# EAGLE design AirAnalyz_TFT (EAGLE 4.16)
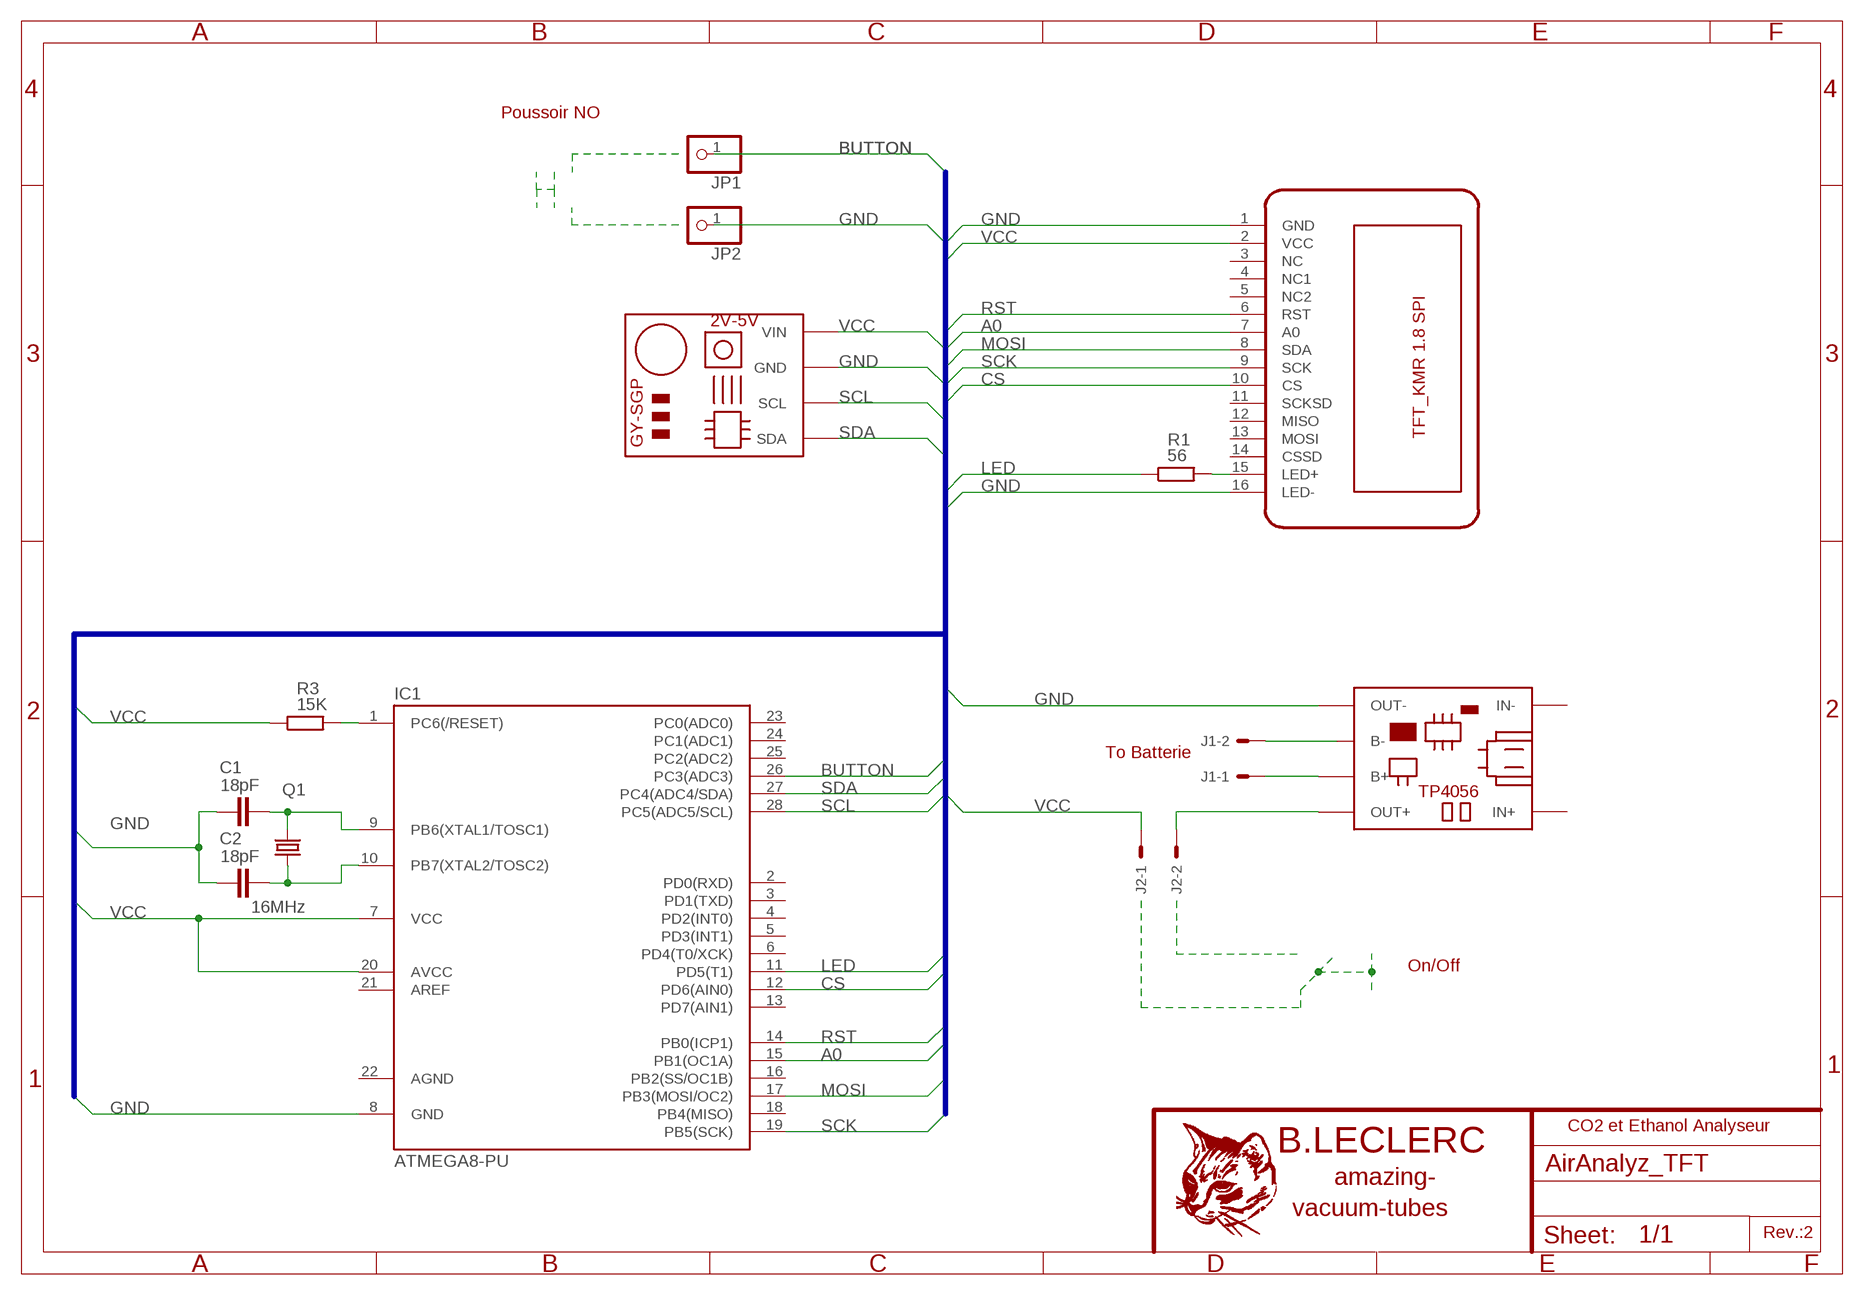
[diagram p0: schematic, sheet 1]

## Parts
C1  18pF  C-EU050-025X075  [C050-025X075]
C2  18pF  C-EU050-025X075  [C050-025X075]
IC1  ATMEGA8-PU  [DIL28-3]
J1  22-27-2021-02  [6410-02]
J2  22-27-2021-02  [6410-02]
JP1  PINHD-1X1  [1X01]
JP2  PINHD-1X1  [1X01]
Q1  16MHz  CRYTALHC49S  [HC49/S]
R1  56  R-EU_0207/12  [0207/12]
R3  15K  R-EU_0207/12  [0207/12]
U$2  TFT_KRM1.8SPI  [TFT_KMR1.8SPI]
U$3  SGP30-AIRANALIZER  [SGP30_AIRANALYZER]
U$4  CHARGEUR_ION-LI  [CHARGEUR_ION-LI]

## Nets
A0: IC1.15(PB1(OC1A)) U$2.7(A0)
BUTTON: IC1.26(PC3(ADC3)) JP1.1
CS: IC1.12(PD6(AIN0)) U$2.10(CS)
GND: C1.1 C2.1 IC1.8(GND) JP2.1 U$2.1(GND) U$2.16(LED-) U$3.GND U$4.OUT-
LED: IC1.11(PD5(T1)) R1.1
LED+: R1.2 U$2.15(LED+)
MOSI: IC1.17(PB3(MOSI/OC2)) U$2.8(SDA)
N$2: J1.2 U$4.B-
N$3: C1.2 IC1.9(PB6(XTAL1/TOSC1)) Q1.2
N$5: IC1.1(PC6(/RESET)) R3.2
N$6: C2.2 IC1.10(PB7(XTAL2/TOSC2)) Q1.1
N$7: J1.1 U$4.B+
N$8: J2.2 U$4.OUT+
RST: IC1.14(PB0(ICP1)) U$2.6(RST)
SCK: IC1.19(PB5(SCK)) U$2.9(SCK)
SCL: IC1.28(PC5(ADC5/SCL)) U$3.SCL
SDA: IC1.27(PC4(ADC4/SDA)) U$3.SDA
VCC: IC1.7(VCC) IC1.20(AVCC) J2.1 R3.1 U$2.2(VCC) U$3.VIN
Unconnected: IC1.2(PD0(RXD)) IC1.3(PD1(TXD)) IC1.4(PD2(INT0)) IC1.5(PD3(INT1)) IC1.6(PD4(T0/XCK)) IC1.13(PD7(AIN1)) IC1.16(PB2(SS/OC1B)) IC1.18(PB4(MISO)) IC1.21(AREF) IC1.23(PC0(ADC0)) IC1.24(PC1(ADC1)) IC1.25(PC2(ADC2)) U$2.3(NC) U$2.4(NC1) U$2.5(NC2) U$2.11(SCKSD) U$2.12(MISO) U$2.13(MOSI) U$2.14(CSSD)

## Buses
B$1

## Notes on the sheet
- Poussoir NO
- To Batterie
- On/Off
- CO2 et Ethanol Analyseur
- Rev.:2

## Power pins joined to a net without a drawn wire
AGND: IC1.22(AGND)
IN+: U$4.IN+
IN-: U$4.IN-

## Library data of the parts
C1 C2 = rcl:C-EU: CAPACITOR, European symbol
IC1 = atmega8:ATMEGA8-PU
J1 J2 = con-molex:22-?-02: CONNECTOR
JP1 JP2 = pinhead:PINHD-1X1: PIN HEADER
Q1 = crystal:CRYTAL: CRYSTAL
R1 R3 = rcl:R-EU_: RESISTOR, European symbol
U$2 = Arduino:TFT_KRM1.8SPI
U$3 = Arduino:SGP30-AIRANALIZER
U$4 = Arduino:CHARGEUR_ION-LI

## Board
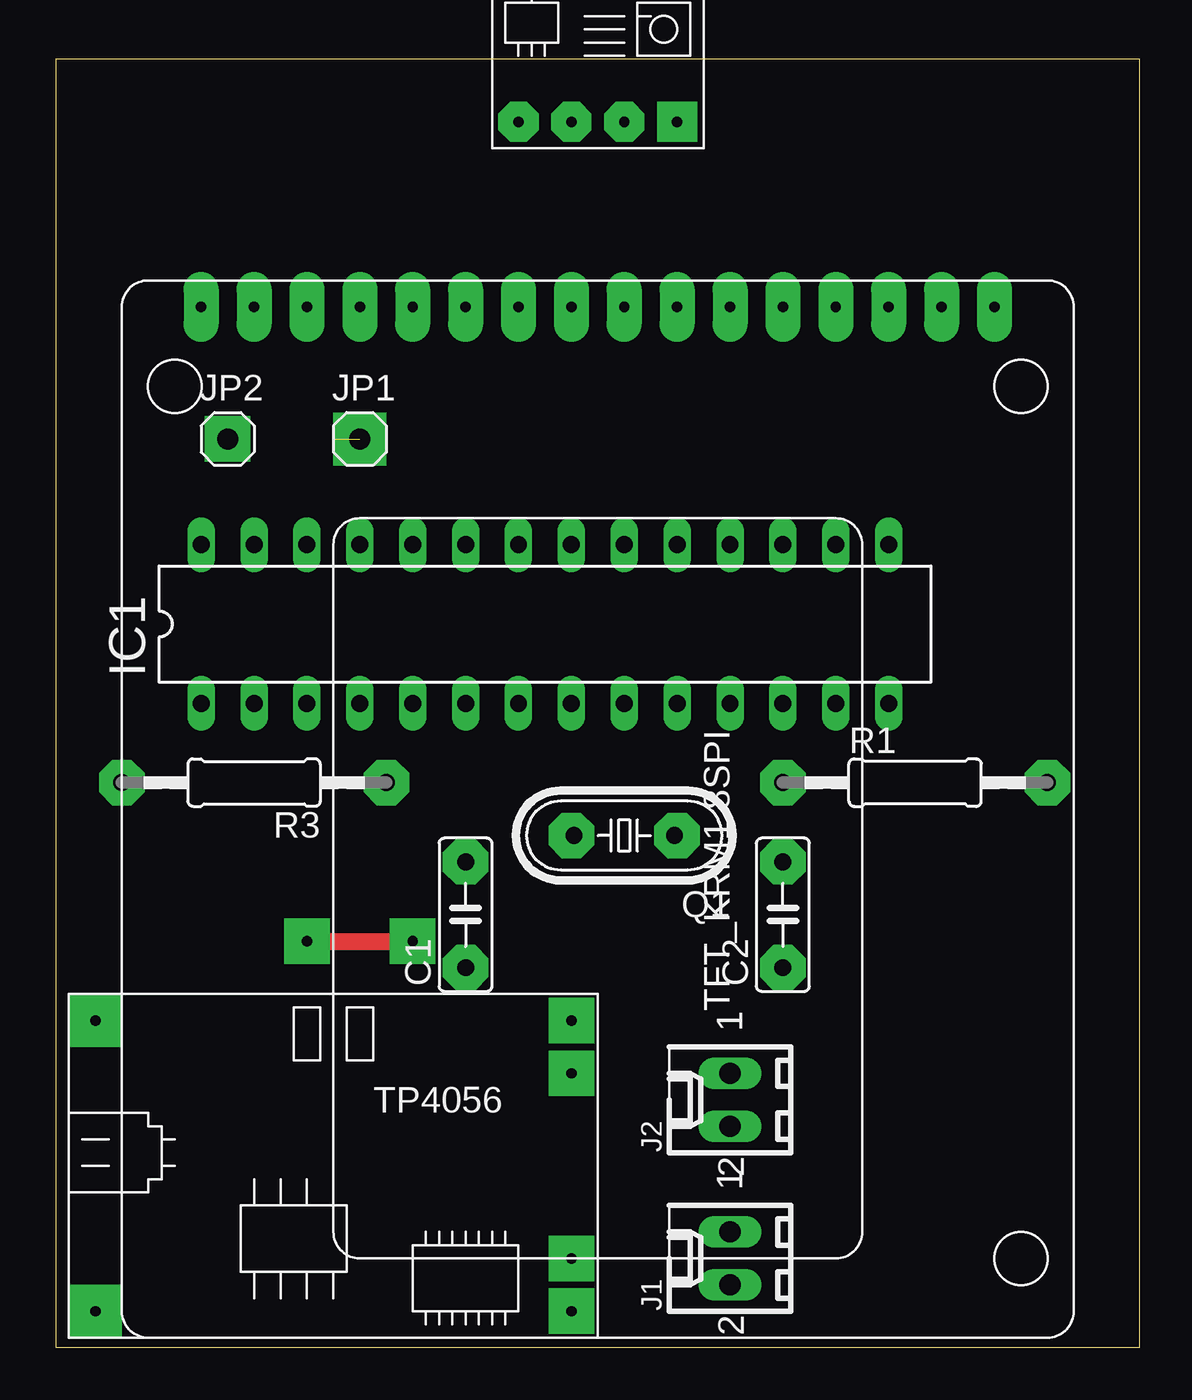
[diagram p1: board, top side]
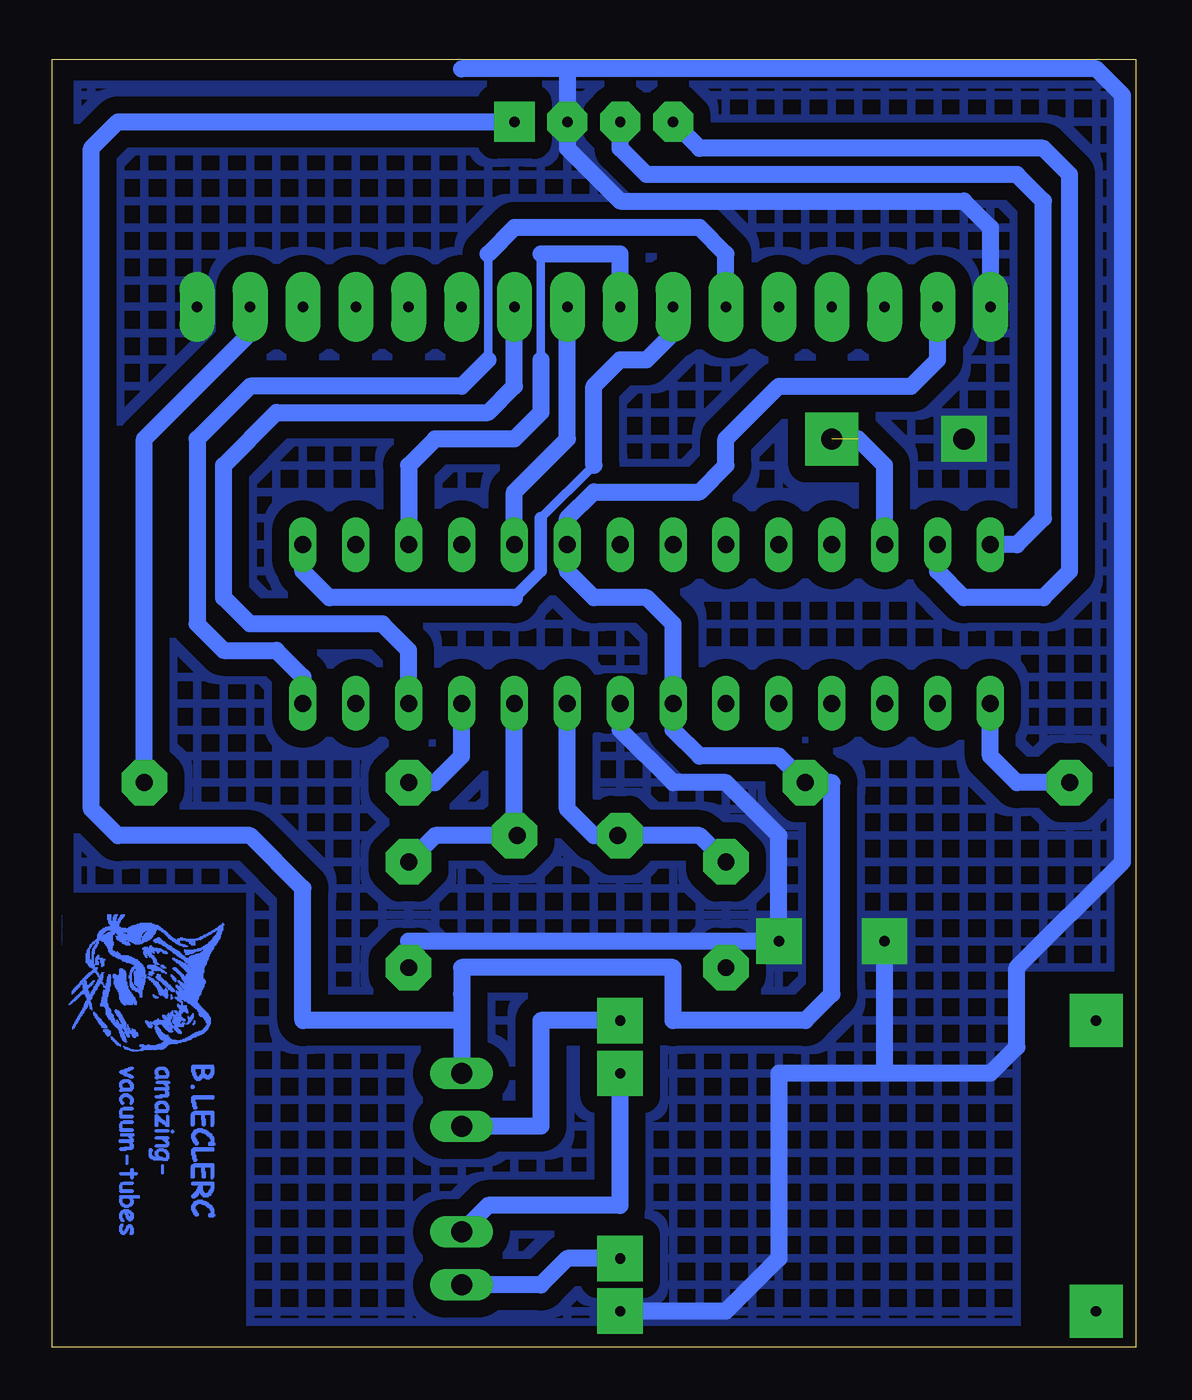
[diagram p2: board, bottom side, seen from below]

Size 52.05 x 61.9 mm. Coordinates in mm from the lower left corner, seen from the top.
Outline: 0,0 52.05,0 52.05,61.9 0,61.9 0,0
Copper layers (1*16): Top 0.035mm / dielectric 1.5mm / Bottom 0.035mm
Design rules "default": minimum track width 10mil, minimum drill 24mil, track to track 8mil, track to pad 8mil, pad to pad 8mil, via to via 8mil, smd to smd 8mil, copper to edge 40mil, drill to drill 8mil, minimum pad ring 10mil, minimum via ring 8mil, stop-mask expansion 4mil, vias tented up to drill 0mil, thermal gap 10mil

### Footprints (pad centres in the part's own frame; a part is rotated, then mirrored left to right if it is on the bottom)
C050-025X075 = drill 0.813 octagon: 1 -2.54,0; 2 2.54,0
DIL28-3 = drill 0.813 long: 1 -16.51,-3.81; 2 -13.97,-3.81; 3 -11.43,-3.81; 4 -8.89,-3.81; 5 -6.35,-3.81; 6 -3.81,-3.81; 7 -1.27,-3.81; 8 1.27,-3.81; 9 3.81,-3.81; 10 6.35,-3.81; 11 8.89,-3.81; 12 11.43,-3.81; 13 13.97,-3.81; 14 16.51,-3.81; 15 16.51,3.81; 16 13.97,3.81; 17 11.43,3.81; 18 8.89,3.81; 19 6.35,3.81; 20 3.81,3.81; 21 1.27,3.81; 22 -1.27,3.81; 23 -3.81,3.81; 24 -6.35,3.81; 25 -8.89,3.81; 26 -11.43,3.81; 27 -13.97,3.81; 28 -16.51,3.81
6410-02 = drill 1.016 long: 1 1.27,0; 2 -1.27,0
1X01 = drill 1.016 octagon: 1 0,0
HC49/S = drill 0.813 round: 1 -2.413,0; 2 2.413,0
0207/12 = drill 0.813 octagon: 1 -6.35,0; 2 6.35,0
TFT_KMR1.8SPI = drill 0.5 pad 1.676 long: 1 -24.13,-19.05; 2 -24.13,-16.51; 3 -24.13,-13.97; 4 -24.13,-11.43; 5 -24.13,-8.89; 6 -24.13,-6.35; 7 -24.13,-3.81; 8 -24.13,-1.27; 9 -24.13,1.27; 10 -24.13,3.81; 11 -24.13,6.35; 12 -24.13,8.89; 13 -24.13,11.43; 14 -24.13,13.97; 15 -24.13,16.51; 16 -24.13,19.05
SGP30_AIRANALYZER = drill 0.5 pad 1.93 octagon: GND 1.27,3.81; SCL 1.27,6.35; SDA 1.27,8.89 | drill 0.5 pad 1.93 square: VIN 1.27,1.27
CHARGEUR_ION-LI = drill 0.5 pad 2.184 square: B+ 24.13,12.7; B- 24.13,3.81; OUT+ 24.13,15.24; OUT- 24.13,1.27 | drill 0.5 pad 2.54 square: IN+ 1.27,15.24; IN- 1.27,1.27

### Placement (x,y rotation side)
C1  19.68,20.79 90 top
C2  34.92,20.79 90 top
IC1  23.49,34.76 0 top
J1  32.38,4.28 90 top
J2  32.38,11.9 90 top
JP1  14.6,43.65 0 top
JP2  8.25,43.65 0 top
Q1  27.3,24.6 180 top
R1  41.27,27.14 0 top
R3  9.52,27.14 180 top
U$2  26.03,25.87 270 top
U$3  31.11,57.62 90 top
U$4  0.63,0.47 0 top
U$5  [CHAT]  51.43,20.79 270 bottom

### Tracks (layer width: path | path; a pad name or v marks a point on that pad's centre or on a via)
A0
  Bottom 0.406: 28.57,39.84 26.03,42.38
  Bottom 0.61: 28.57,39.84 28.57,37.3 29.84,36.03
  Bottom 0.813: U$2.7 22.22,48.73 23.49,47.46 24.76,47.46 26.03,46.19 26.03,42.38 | 29.84,36.03 38.73,36.03 40,37.3 IC1.15
BUTTON  (1 unrouted)
  Bottom 0.813: 13.33,43.65 12.06,42.38 IC1.26
CS
  Bottom 0.813: U$2.10 29.84,46.19 31.11,44.92 41.27,44.92 43.81,42.38 43.81,36.03 42.54,34.76 36.19,34.76 34.92,33.49 IC1.12
GND  (via drill 0.5 pad 2.18)
  Top 0.813: v12.06,19.52 v17.14,19.52
  Bottom 0.813: U$2.1 6.98,53.81 8.25,55.08 24.76,55.08 27.3,57.62 U$3.GND 27.3,61.43 | U$4.OUT- 19.68,1.74 17.14,4.28 17.14,13.17 12.06,13.17 | IC1.8 24.76,29.68 22.22,27.14 19.68,27.14 17.14,24.6 v17.14,19.52 19.68,19.52 | 27.3,61.43 32.38,61.43 | 27.3,61.43 1.9,61.43 0.63,60.16 0.63,23.33 5.71,18.25 5.71,14.44 6.98,13.17 12.06,13.17 | 12.06,13.17 v12.06,19.52 | 19.68,19.52 34.92,19.52 C2.1 | 19.68,19.52 C1.1
  other vias: 8.25,43.65
  pour Bottom (isolate 0.813, no thermals, hatched): 5.71,0.47 5.71,18.25 0.63,18.25 0.63,61.43 51.43,61.43 51.43,22.06 42.54,22.06 42.54,0.47
LED
  Bottom 0.813: IC1.11 32.38,28.41 33.65,27.14 R1.1
LED+
  Bottom 0.813: U$2.15 42.54,48.73 47.62,43.65 R1.2
MOSI
  Bottom 0.406: 28.57,52.54 28.57,47.46
  Bottom 0.813: IC1.17 34.92,42.38 33.65,43.65 29.84,43.65 28.57,44.92 28.57,47.46 | 28.57,52.54 24.76,52.54 U$2.8
N$2
  Bottom 0.813: U$4.B- 27.3,4.28 28.57,3.01 J1.2
N$3
  Bottom 0.813: IC1.9 27.3,25.87 26.03,24.6 Q1.2 20.95,24.6 C1.2
N$5
  Bottom 0.813: IC1.1 6.98,28.41 5.71,27.14 R3.2
N$6
  Bottom 0.813: 29.84,24.6 IC1.10 | Q1.1 29.84,24.6 | 29.84,24.6 33.65,24.6 C2.2
N$7
  Bottom 0.813: U$4.B+ 24.76,6.82 31.11,6.82 J1.1
N$8
  Bottom 0.813: U$4.OUT+ 28.57,15.71 28.57,10.63 J2.2
N$10  (via drill 0.5 pad 1.27)
  other vias: 17.14,38.57
N$11  (via drill 0.5 pad 1.27)
  other vias: 14.6,38.57
N$12  (via drill 0.5 pad 1.27)
  other vias: 19.68,38.57
N$13  (via drill 0.5 pad 1.27)
  other vias: 6.98,30.95
N$14  (via drill 0.5 pad 1.27)
  other vias: 29.84,38.57
N$15  (via drill 0.5 pad 1.27)
  other vias: 12.06,30.95
N$16  (via drill 0.5 pad 1.27)
  other vias: 24.76,38.57
N$17  (via drill 0.5 pad 1.27)
  other vias: 22.22,38.57
N$18  (via drill 0.5 pad 1.27)
  other vias: 27.3,38.57
N$19  (via drill 0.5 pad 1.27)
  other vias: 32.38,38.57
N$20  (via drill 0.5 pad 1.27)
  other vias: 24.76,30.95
N$21  (via drill 0.5 pad 1.27)
  other vias: 19.68,30.95
N$22  (via drill 0.5 pad 1.27)
  other vias: 27.3,30.95
N$23  (via drill 0.5 pad 1.27)
  other vias: 32.38,30.95
N$24  (via drill 0.5 pad 1.27)
  other vias: 34.92,30.95
N$25  (via drill 0.5 pad 1.27)
  other vias: 37.46,38.57
N$26  (via drill 0.5 pad 1.27)
  other vias: 34.92,38.57
N$27  (via drill 0.5 pad 1.27)
  other vias: 40,38.57
N$28  (via drill 0.5 pad 1.27)
  other vias: 40,30.95
N$29  (via drill 0.5 pad 1.27)
  other vias: 37.46,30.95
N$30  (via drill 0.5 pad 1.27)
  other vias: 29.84,30.95
N$31  (via drill 0.5 pad 1.27)
  other vias: 22.22,30.95
N$32  (via drill 0.5 pad 1.27)
  other vias: 17.14,30.95
N$33  (via drill 0.5 pad 1.27)
  other vias: 14.6,30.95
N$34  (via drill 0.5 pad 1.27)
  other vias: 9.52,30.95
N$35  (via drill 0.5 pad 1.27)
  other vias: 12.06,38.57
N$36  (via drill 0.5 pad 1.27)
  other vias: 9.52,38.57
N$37  (via drill 0.5 pad 1.27)
  other vias: 6.98,38.57
N$40  (via drill 0.5 pad 2.18)
  other vias: 15.87,27.14
N$41  (via drill 0.5 pad 2.18)
  other vias: 3.17,27.14
N$42  (via drill 0.5 pad 2.18)
  other vias: 47.62,27.14
N$43  (via drill 0.5 pad 2.18)
  other vias: 34.92,27.14
N$44  (via drill 0.5 pad 2.18)
  other vias: 24.76,24.6
N$45  (via drill 0.5 pad 2.18)
  other vias: 29.84,24.6
N$47  (via drill 0.5 pad 2.18)
  other vias: 19.68,23.33
N$48  (via drill 0.5 pad 2.18)
  other vias: 34.92,23.33
N$50  (via drill 0.5 pad 1.27)
  other vias: 32.38,13.17
N$51  (via drill 0.5 pad 1.27)
  other vias: 32.38,10.63
N$54  (via drill 0.5 pad 1.27)
  other vias: 32.38,5.55
N$55  (via drill 0.5 pad 1.27)
  other vias: 32.38,3.01
N$56  (via drill 0.5 pad 2.54)
  other vias: 14.6,43.65
RST
  Bottom 0.406: 40,32.22 IC1.14 | 31.11,52.54 31.11,47.46
  Bottom 0.813: U$2.6 19.68,52.54 20.95,53.81 29.84,53.81 31.11,52.54 | 31.11,47.46 32.38,46.19 42.54,46.19 45.08,43.65 45.08,34.76 43.81,33.49 41.27,33.49 40,32.22
S$1  (via drill 0.5 pad 2.18)
  other vias: 19.68,18.25
S$2  (via drill 0.5 pad 2.18)
  other vias: 34.92,18.25
SCK
  Bottom 0.813: U$2.9 27.3,43.65 29.84,41.11 IC1.19
SCL
  Bottom 0.813: U$3.SCL 24.76,57.62 23.49,56.35 5.71,56.35 4.44,55.08 4.44,39.84 5.71,38.57 IC1.28
SDA
  Bottom 0.813: IC1.27 9.52,37.3 8.25,36.03 4.44,36.03 3.17,37.3 3.17,56.35 4.44,57.62 20.95,57.62 U$3.SDA
VCC
  Bottom 0.813: U$2.2 9.52,47.46 10.79,46.19 17.14,46.19 19.68,43.65 19.68,42.38 20.95,41.11 26.03,41.11 27.3,39.84 IC1.20 27.3,37.3 26.03,36.03 23.49,36.03 22.22,34.76 IC1.7 22.22,29.68 20.95,28.41 17.14,28.41 R3.1 14.6,27.14 14.6,16.98 15.87,15.71 22.22,15.71 22.22,18.25 32.38,18.25 32.38,16.98 | 32.38,16.98 32.38,15.71 40,15.71 40,22.06 42.54,24.6 48.89,24.6 50.16,25.87 50.16,57.62 48.89,58.89 U$3.VIN | 32.38,16.98 J2.1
